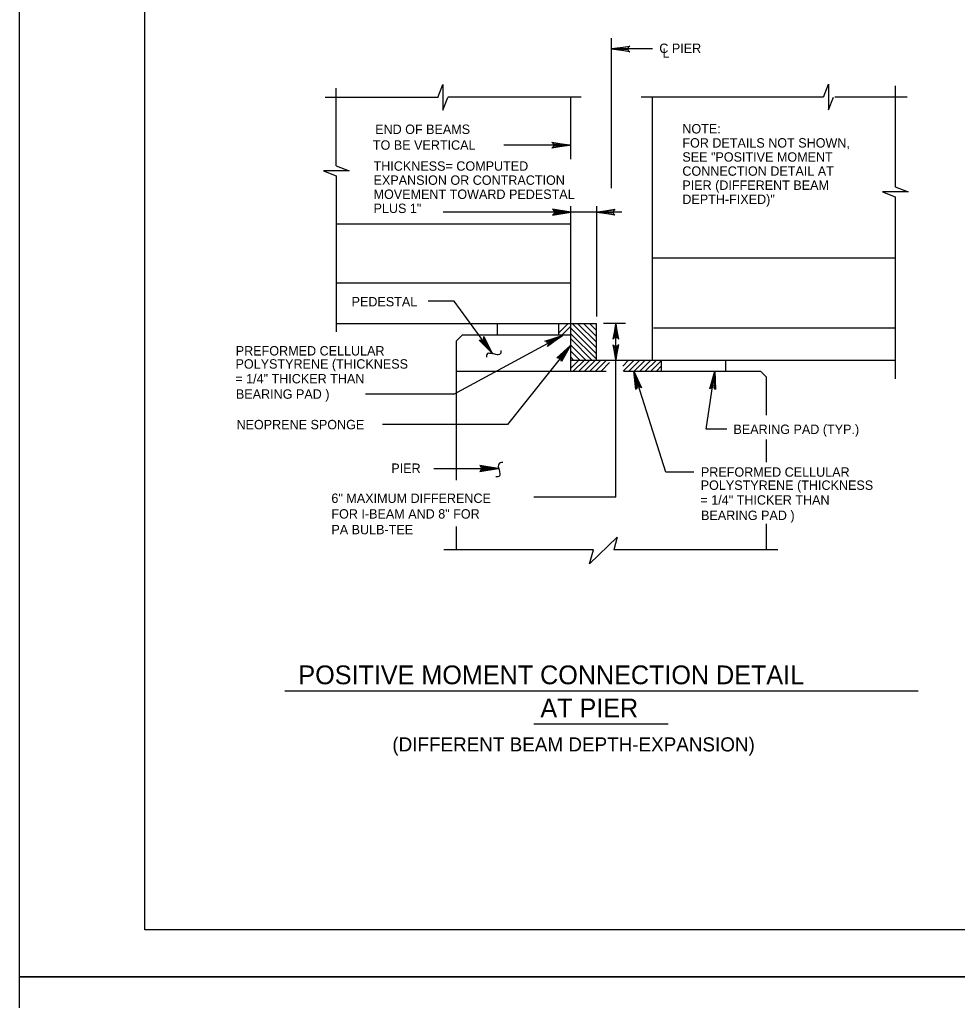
# Model space of a CAD drawing. Extents: x 639980 to 641204, y 298038 to 300414.
# Drawn here: x 639980.3 to 640279.6, y 299218.3 to 299531.3 of the extents above; entities that cross this region are included whole.
import ezdxf

# ---------------------------------------------------------------- set-up
doc = ezdxf.new("R2010")
doc.units = 0
for name, color, linetype in [('1', 7, 'Continuous'), ('2', 7, 'Continuous'), ('3', 7, 'Continuous'), ('PLT-BNDY', 7, 'Continuous')]:
    doc.layers.add(name, color=color, linetype=linetype)

msp = doc.modelspace()

# ---------------------------------------------------------------- linework, layer by layer
at = {"layer": '1'}
for p, q in [((640169.22, 299477.52), (640169.22, 299525.41)), ((640156.2, 299486.8), (640156.2, 299506.54)), ((640182.24, 299422.66), (640182.24, 299506.54)), ((640156.2, 299419.14), (640156.2, 299471.78)), ((640152.36, 299430.8), (640152.36, 299434.32)), ((640185.16, 299419.14), (640185.16, 299422.66)), ((640162.21, 299357.66), (640171.04, 299366.19)), ((640171.04, 299366.19), (640169.89, 299362.13)), ((640162.21, 299357.66), (640163.4, 299362.13))]:
    msp.add_line(p, q, dxfattribs=at)
for points in [[(640133.89, 299425.72), (640133.82, 299424.91), (640133.41, 299424.48), (640132.65, 299424.31), (640131.93, 299424.52), (640131.17, 299424.68), (640130.4, 299424.81), (640129.64, 299424.72), (640129.32, 299424.15), (640129.32, 299423.55)], [(640134.47, 299389.95), (640133.66, 299389.88), (640133.23, 299389.47), (640133.05, 299388.71), (640133.27, 299387.99), (640133.42, 299387.23), (640133.55, 299386.46), (640133.47, 299385.7), (640132.9, 299385.38), (640132.29, 299385.38)]]:
    msp.add_spline(points, degree=3, dxfattribs=at)
at = {"layer": '2'}
for p, q in [((640020.31, 299240.78), (640020.31, 299804.78)), ((640182.24, 299521.99), (640169.22, 299521.99)), ((640113.75, 299506.48), (640115.39, 299510.67)), ((640115.39, 299510.67), (640115.39, 299502.42)), ((640236.82, 299506.6), (640238.45, 299510.78)), ((640238.45, 299510.78), (640238.45, 299502.54)), ((640081.33, 299484.68), (640081.33, 299509.48)), ((640259.78, 299478), (640259.78, 299510.21)), ((640113.75, 299506.48), (640077.81, 299506.48)), ((640115.39, 299502.42), (640116.97, 299506.48)), ((640159.5, 299506.54), (640116.97, 299506.54)), ((640236.64, 299506.54), (640178.62, 299506.54)), ((640238.45, 299502.54), (640240.04, 299506.6)), ((640263.56, 299506.6), (640240.44, 299506.6)), ((640156.01, 299491.26), (640134.85, 299491.26)), ((640085.51, 299483.05), (640077.27, 299483.05)), ((640077.27, 299483.05), (640081.33, 299481.46)), ((640081.33, 299484.68), (640085.51, 299483.05)), ((640081.38, 299431.67), (640081.38, 299481.46)), ((640263.9, 299476.36), (640255.66, 299476.36)), ((640255.66, 299476.36), (640259.71, 299474.78)), ((640259.71, 299478), (640263.9, 299476.36)), ((640259.78, 299416.7), (640259.78, 299474.78)), ((640156.2, 299469.87), (640115.44, 299469.87)), ((640164.36, 299469.87), (640156.2, 299469.87)), ((640164.36, 299471.78), (640164.36, 299436.55)), ((640172.51, 299469.87), (640164.36, 299469.87)), ((640081.38, 299466.16), (640156.2, 299466.16)), ((640182.24, 299455.33), (640259.78, 299455.33)), ((640081.38, 299447.34), (640156.2, 299447.34)), ((640119.02, 299441.52), (640110.71, 299441.52)), ((640131.08, 299424.86), (640119.02, 299441.52)), ((640081.38, 299434.32), (640164.36, 299434.32)), ((640132.77, 299430.8), (640132.77, 299434.32)), ((640152.36, 299431.41), (640155.32, 299434.36)), ((640153.49, 299430.77), (640156.2, 299433.48)), ((640156.2, 299432.86), (640164.36, 299424.7)), ((640156.65, 299434.33), (640164.36, 299426.62)), ((640158.39, 299434.32), (640164.36, 299428.35)), ((640160.23, 299434.32), (640164.36, 299430.19)), ((640162.12, 299434.32), (640164.36, 299432.09)), ((640164.36, 299422.69), (640164.36, 299434.32)), ((640173.63, 299434.32), (640166.59, 299434.32)), ((640170.56, 299422.66), (640170.56, 299434.24)), ((640182.57, 299432.96), (640259.78, 299432.96)), ((640119.74, 299428.85), (640121.67, 299430.77)), ((640119.74, 299385.12), (640119.74, 299428.85)), ((640121.67, 299430.77), (640156.2, 299430.77)), ((640156.2, 299431.07), (640164.36, 299422.91)), ((640156.2, 299429.41), (640162.96, 299422.66)), ((640118.91, 299411.78), (640149.89, 299428.6)), ((640156.09, 299427.31), (640136.05, 299402.15)), ((640156.2, 299427.47), (640161.02, 299422.66)), ((640156.2, 299425.53), (640159.07, 299422.66)), ((640156.2, 299423.58), (640157.1, 299422.69)), ((640156.2, 299422.66), (640259.78, 299422.66)), ((640156.2, 299420.11), (640158.75, 299422.66)), ((640157, 299419.14), (640160.52, 299422.66)), ((640158.77, 299419.14), (640162.29, 299422.66)), ((640160.54, 299419.14), (640164.06, 299422.66)), ((640162.3, 299419.14), (640165.82, 299422.66)), ((640164.07, 299419.14), (640167.59, 299422.66)), ((640170.56, 299378.88), (640170.56, 299422.66)), ((640172.76, 299420.76), (640174.66, 299422.66)), ((640172.91, 299419.14), (640176.43, 299422.66)), ((640174.68, 299419.14), (640178.2, 299422.66)), ((640176.45, 299419.14), (640179.97, 299422.66)), ((640178.21, 299419.14), (640181.73, 299422.66)), ((640179.98, 299419.14), (640183.5, 299422.66)), ((640205.68, 299419.14), (640205.68, 299422.66)), ((640165.84, 299419.14), (640168.59, 299421.89)), ((640181.75, 299419.14), (640185.16, 299422.55)), ((640183.52, 299419.14), (640185.16, 299420.78)), ((640119.74, 299419.14), (640167.48, 299419.14)), ((640173.11, 299419.14), (640216.75, 299419.14)), ((640186.51, 299386.84), (640176.27, 299419.14)), ((640199.35, 299400.59), (640202.18, 299419.14)), ((640218.7, 299417.18), (640216.75, 299419.14)), ((640218.7, 299405.07), (640218.7, 299417.18)), ((640118.91, 299411.78), (640090.67, 299411.78)), ((640136.05, 299402.15), (640096.09, 299402.15)), ((640205.97, 299400.59), (640199.35, 299400.59)), ((640218.7, 299390.13), (640218.7, 299397.3)), ((640119.74, 299384.37), (640119.74, 299388.46)), ((640112.47, 299388.07), (640133.02, 299388.07)), ((640195.48, 299386.84), (640186.51, 299386.84)), ((640170.56, 299378.88), (640144.42, 299378.88)), ((640119.74, 299362.13), (640119.74, 299369.53)), ((640218.7, 299362.13), (640218.7, 299370.4)), ((640163.4, 299362.13), (640115.68, 299362.13)), ((640222.23, 299362.13), (640169.89, 299362.13)), ((640064.93, 299317.14), (640267.05, 299317.14)), ((640144.37, 299306.55), (640187.31, 299306.55)), ((640806.31, 299240.78), (640020.31, 299240.78))]:
    msp.add_line(p, q, dxfattribs=at)
for points in [[(640174.76, 299521.3), (640174.55, 299521.7), (640169.22, 299521.99), (640174.76, 299521.3), (640175.04, 299521.05), (640169.22, 299521.99), (640174.55, 299522.25), (640174.74, 299522.65), (640169.22, 299521.99), (640175.04, 299522.91), (640174.74, 299522.65)], [(640150.48, 299491.95), (640150.68, 299491.55), (640156.01, 299491.26), (640150.48, 299491.95), (640150.19, 299492.19), (640156.01, 299491.26), (640150.69, 299490.99), (640150.49, 299490.6), (640156.01, 299491.26), (640150.19, 299490.33), (640150.49, 299490.6)], [(640150.67, 299469.17), (640150.87, 299469.57), (640156.2, 299469.87), (640150.67, 299469.17), (640150.38, 299468.93), (640156.2, 299469.87), (640150.88, 299470.13), (640150.68, 299470.53), (640156.2, 299469.87), (640150.38, 299470.79), (640150.68, 299470.53)], [(640170.02, 299469.17), (640169.81, 299469.57), (640164.48, 299469.87), (640170.02, 299469.17), (640170.3, 299468.93), (640164.48, 299469.87), (640169.81, 299470.13), (640170, 299470.53), (640164.48, 299469.87), (640170.3, 299470.79), (640170, 299470.53)], [(640171.25, 299429.62), (640170.85, 299429.8), (640170.56, 299434.24), (640171.25, 299429.62), (640171.5, 299429.39), (640170.56, 299434.24), (640170.29, 299429.8), (640169.9, 299429.64), (640170.56, 299434.24), (640169.63, 299429.39), (640169.9, 299429.64)], [(640128.44, 299429.78), (640128.23, 299429.38), (640131.08, 299424.86), (640128.44, 299429.78), (640128.48, 299430.15), (640131.08, 299424.86), (640127.78, 299429.05), (640127.35, 299428.98), (640131.08, 299424.86), (640126.96, 299429.07), (640127.35, 299428.98)], [(640148.3, 299428.6), (640148.67, 299428.34), (640153.54, 299430.53), (640148.3, 299428.6), (640147.94, 299428.69), (640153.54, 299430.53), (640148.93, 299427.85), (640148.94, 299427.41), (640153.54, 299430.53), (640148.8, 299427.03), (640148.94, 299427.41)], [(640152.1, 299423.42), (640152.54, 299423.33), (640156.09, 299427.31), (640152.1, 299423.42), (640151.73, 299423.34), (640156.09, 299427.31), (640152.98, 299422.98), (640153.17, 299422.58), (640156.09, 299427.31), (640153.19, 299422.18), (640153.17, 299422.58)], [(640169.86, 299427.34), (640170.26, 299427.17), (640170.56, 299422.73), (640169.86, 299427.34), (640169.62, 299427.58), (640170.56, 299422.73), (640170.82, 299427.16), (640171.22, 299427.33), (640170.56, 299422.73), (640171.48, 299427.58), (640171.22, 299427.33)], [(640177.11, 299413.62), (640177.44, 299413.93), (640176.27, 299419.14), (640177.11, 299413.62), (640176.95, 299413.28), (640176.27, 299419.14), (640177.97, 299414.08), (640178.41, 299414.01), (640176.27, 299419.14), (640178.74, 299413.79), (640178.41, 299414.01)], [(640200.83, 299413.72), (640201.25, 299413.88), (640202.18, 299419.14), (640200.83, 299413.72), (640200.55, 299413.47), (640202.18, 299419.14), (640201.8, 299413.82), (640202.17, 299413.58), (640202.18, 299419.14), (640202.4, 299413.25), (640202.17, 299413.58)], [(640127.49, 299387.38), (640127.69, 299387.78), (640133.02, 299388.07), (640127.49, 299387.38), (640127.2, 299387.14), (640133.02, 299388.07), (640127.7, 299388.34), (640127.5, 299388.73), (640133.02, 299388.07), (640127.2, 299389), (640127.5, 299388.73)]]:
    msp.add_lwpolyline(points, dxfattribs=at)
at = {"layer": 'PLT-BNDY'}
for points in [[(639980.31, 299819.78), (640821.31, 299819.78), (640821.31, 299225.78), (639980.31, 299225.78)], [(639980.31, 299225.78), (640821.31, 299225.78), (640821.31, 298631.78), (639980.31, 298631.78)]]:
    msp.add_lwpolyline(points, close=True, dxfattribs=at)

# ---------------------------------------------------------------- texts
at = {"layer": '2'}
for s, height, p in [('POSITIVE MOMENT CONNECTION DETAIL', 6, (640069.28, 299319.19)), ('AT PIER', 6, (640146.5, 299308.61)), ('(DIFFERENT BEAM DEPTH-EXPANSION)', 4.5, (640099.25, 299297.75))]:
    msp.add_text(s, height=height, dxfattribs=at).set_placement(p)
at = {"layer": '3'}
for s, height, p in [('C PIER', 2.999, (640184.44, 299520.69)), ('L', 3, (640185.46, 299519.23)), ('END OF BEAMS', 2.9989, (640093.77, 299494.84)), ('NOTE:', 2.999, (640191.8, 299495)), ('TO BE VERTICAL', 2.9989, (640093.04, 299489.81)), ('FOR DETAILS NOT SHOWN,', 2.9989, (640191.8, 299490.5)), ('SEE "POSITIVE MOMENT', 2.9989, (640191.8, 299486)), ('THICKNESS= COMPUTED', 2.9989, (640093.26, 299483.11)), ('CONNECTION DETAIL AT', 2.9989, (640191.8, 299481.5)), ('EXPANSION OR CONTRACTION', 2.9989, (640093.26, 299478.61)), ('PIER (DIFFERENT BEAM', 2.9989, (640191.8, 299477)), ('MOVEMENT TOWARD PEDESTAL', 2.9989, (640093.26, 299474.11)), ('DEPTH-FIXED)"', 2.9989, (640191.8, 299472.5)), ('PLUS 1"', 2.999, (640093.26, 299469.61)), ('PEDESTAL', 2.999, (640086.25, 299439.81)), ('PREFORMED CELLULAR', 2.9989, (640049.29, 299424.13)), ('POLYSTYRENE (THICKNESS ', 2.9989, (640049.21, 299419.94)), ('= 1/4" THICKER THAN', 2.9989, (640049.14, 299415.22)), ('BEARING PAD )', 2.9989, (640049.33, 299410.32)), ('NEOPRENE SPONGE', 2.9989, (640049.52, 299400.58)), ('BEARING PAD (TYP.)', 2.9989, (640208.11, 299399.08)), ('PIER', 2.999, (640098.92, 299386.66)), ('PREFORMED CELLULAR', 2.9989, (640197.72, 299385.43)), ('POLYSTYRENE (THICKNESS ', 2.9989, (640197.65, 299381.24)), ('6" MAXIMUM DIFFERENCE', 2.9999, (640079.8, 299377.07)), ('= 1/4" THICKER THAN', 2.9989, (640197.57, 299376.52)), ('FOR I-BEAM AND 8" FOR', 2.9999, (640079.8, 299372.07)), ('BEARING PAD )', 2.9989, (640197.76, 299371.62)), ('PA BULB-TEE', 2.9999, (640079.8, 299367.07))]:
    msp.add_text(s, height=height, dxfattribs=at).set_placement(p)

doc.saveas('drawing.dxf')
